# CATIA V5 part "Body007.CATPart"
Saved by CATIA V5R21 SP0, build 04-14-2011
Part number: Body007
Definition: design
Nomenclature: Body007
Source: Unknown
Bounding box of the stored display mesh (mm): x -0.6 to 0.6, y -0.4 to 0.4, z 0 to 1
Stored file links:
  C:\Users\beatr\OneDrive\Documents\UNB\2026_1\Pi1\Componentes eletronicos\Encoder\Body007.CATPart
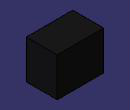
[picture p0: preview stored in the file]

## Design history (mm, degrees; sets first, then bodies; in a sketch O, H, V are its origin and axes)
Body1 "MANIFOLD_SOLID_BREP #4489" (main body)
  Solid1: solid without history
